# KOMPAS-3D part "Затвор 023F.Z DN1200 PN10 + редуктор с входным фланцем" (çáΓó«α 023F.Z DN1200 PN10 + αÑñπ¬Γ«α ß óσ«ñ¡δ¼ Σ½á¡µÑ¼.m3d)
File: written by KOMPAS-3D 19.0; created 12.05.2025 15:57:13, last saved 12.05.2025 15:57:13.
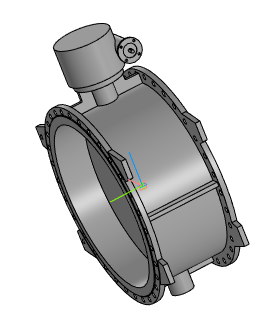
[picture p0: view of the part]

Document properties: Полное имя файла: ..\Затвор 023F.Z DN1200 PN10 + редуктор с входным фланцем.a3d

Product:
- Part/product: Затвор 023F.Z DN1200 PN10 + редуктор с входным фланцем
    Масса: 2055.8

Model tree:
1. Операция без истории:1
